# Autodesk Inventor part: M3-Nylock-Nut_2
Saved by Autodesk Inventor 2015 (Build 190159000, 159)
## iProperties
Created: 2015-01
Part Number: M3-Nylock-Nut_2
Material: Steel, Galvanized
Document SubType Name: Modeling
Designer: TODD D MILLER
Mass: 0.554619 g
Surface Area: 1.47755 cm^2
Volume: 0.0706521 cm^3
Density: 7.85 g/cm^3
Appearance: Galvanized
Author: TODD D MILLER
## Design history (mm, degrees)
node "M3-Nylock-Nut_2.ipt1"
node "M3-Nylock-Nut"
node "Base1"
